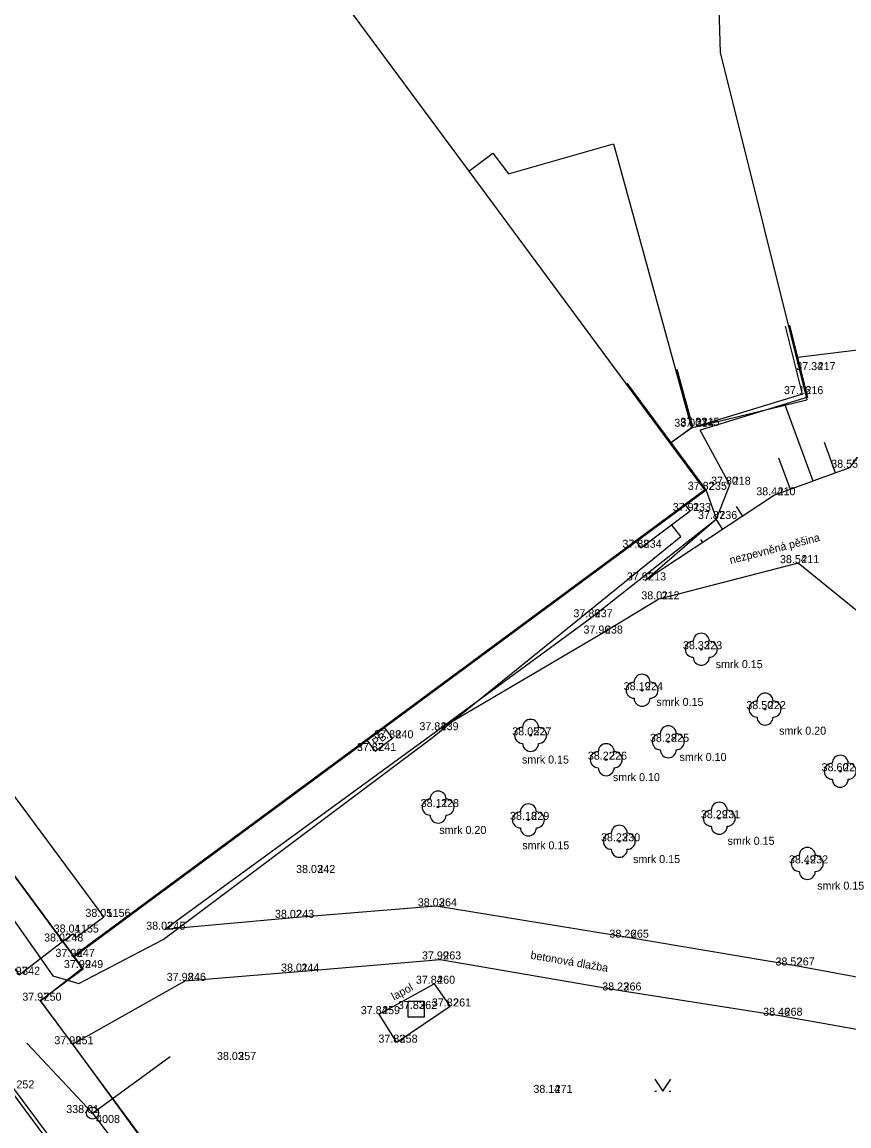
# Model space of a CAD drawing. Extents: x -609709 to -609357, y -1051535 to -1051131.
# Drawn here: x -609544.11 to -609518.29, y -1051297.25 to -1051262.77 of the extents above; entities that cross this region are included whole.
import ezdxf

# ---------------------------------------------------------------- set-up
doc = ezdxf.new("R2010")
doc.units = 0
for name, color, linetype in [('Vrstva 1', 7, 'Continuous'), ('Vrstva 10', 7, 'Continuous'), ('Vrstva 12', 7, 'Continuous'), ('Vrstva 18', 7, 'Continuous'), ('Vrstva 2', 7, 'Continuous'), ('Vrstva 3', 7, 'Continuous'), ('Vrstva 4', 7, 'Continuous'), ('Vrstva 5', 7, 'Continuous'), ('Vrstva 6', 7, 'Continuous'), ('Vrstva 7', 7, 'Continuous'), ('Vrstva 8', 7, 'Continuous'), ('Vrstva 9', 7, 'Continuous')]:
    doc.layers.add(name, color=color, linetype=linetype)

msp = doc.modelspace()

# ---------------------------------------------------------------- linework, layer by layer
at = {"layer": 'Vrstva 1'}
for p, q in [((-609519.36, -1051273.64), (-609519.36, -1051273.64)), ((-609519.74, -1051274.39), (-609519.74, -1051274.39)), ((-609523.16, -1051275.41), (-609523.16, -1051275.41)), ((-609522.98, -1051275.38), (-609522.98, -1051275.38)), ((-609522.01, -1051277.22), (-609522.01, -1051277.22)), ((-609522.75, -1051277.38), (-609522.75, -1051277.38)), ((-609520.61, -1051277.55), (-609520.61, -1051277.55)), ((-609523.25, -1051278.04), (-609523.25, -1051278.04)), ((-609522.43, -1051278.29), (-609522.43, -1051278.29)), ((-609524.79, -1051279.19), (-609524.79, -1051279.19)), ((-609519.87, -1051279.67), (-609519.87, -1051279.67)), ((-609524.65, -1051280.21), (-609524.65, -1051280.21)), ((-609524.23, -1051280.8), (-609524.23, -1051280.8)), ((-609526.32, -1051281.36), (-609526.32, -1051281.36)), ((-609526, -1051281.87), (-609526, -1051281.87)), ((-609522.9, -1051282.36), (-609522.9, -1051282.36)), ((-609524.75, -1051283.64), (-609524.75, -1051283.64)), ((-609520.91, -1051284.23), (-609520.91, -1051284.23)), ((-609532.54, -1051285.14), (-609532.54, -1051285.14)), ((-609531.13, -1051284.89), (-609531.13, -1051284.89)), ((-609528.23, -1051285.05), (-609528.23, -1051285.05)), ((-609533.08, -1051285.54), (-609533.08, -1051285.54)), ((-609523.93, -1051285.25), (-609523.93, -1051285.25)), ((-609525.87, -1051285.81), (-609525.87, -1051285.81)), ((-609518.56, -1051286.17), (-609518.56, -1051286.17)), ((-609531.12, -1051287.29), (-609531.12, -1051287.29)), ((-609528.3, -1051287.69), (-609528.3, -1051287.69)), ((-609522.34, -1051287.64), (-609522.34, -1051287.64)), ((-609525.46, -1051288.36), (-609525.46, -1051288.36)), ((-609534.98, -1051289.35), (-609534.98, -1051289.35)), ((-609519.59, -1051289.05), (-609519.59, -1051289.05)), ((-609531.18, -1051290.39), (-609531.18, -1051290.39)), ((-609541.56, -1051290.72), (-609541.56, -1051290.72)), ((-609535.64, -1051290.75), (-609535.64, -1051290.75)), ((-609542.55, -1051291.21), (-609542.55, -1051291.21)), ((-609539.66, -1051291.12), (-609539.66, -1051291.12)), ((-609525.19, -1051291.37), (-609525.19, -1051291.37)), ((-609542.85, -1051291.49), (-609542.85, -1051291.49)), ((-609542.49, -1051291.97), (-609542.49, -1051291.97)), ((-609531.05, -1051292.05), (-609531.05, -1051292.05)), ((-609542.23, -1051292.32), (-609542.23, -1051292.32)), ((-609535.48, -1051292.43), (-609535.48, -1051292.43)), ((-609520.01, -1051292.24), (-609520.01, -1051292.24)), ((-609539.02, -1051292.72), (-609539.02, -1051292.72)), ((-609531.24, -1051292.81), (-609531.24, -1051292.81)), ((-609525.42, -1051293.02), (-609525.42, -1051293.02)), ((-609543.53, -1051293.34), (-609543.53, -1051293.34)), ((-609532.96, -1051293.76), (-609532.96, -1051293.76)), ((-609531.8, -1051293.6), (-609531.8, -1051293.6)), ((-609530.74, -1051293.52), (-609530.74, -1051293.52)), ((-609520.39, -1051293.81), (-609520.39, -1051293.81)), ((-609542.53, -1051294.7), (-609542.53, -1051294.7)), ((-609532.41, -1051294.65), (-609532.41, -1051294.65)), ((-609537.45, -1051295.19), (-609537.45, -1051295.19)), ((-609527.57, -1051296.22), (-609527.57, -1051296.22)), ((-609541.91, -1051296.85), (-609541.91, -1051296.85))]:
    msp.add_line(p, q, dxfattribs=at)
at = {"layer": 'Vrstva 10'}
for p, q in [((-609573.93, -1051249.42), (-609542.5, -1051291.94)), ((-609522.44, -1051259.04), (-609522.31, -1051263.72)), ((-609535.71, -1051259.91), (-609530.16, -1051267.42)), ((-609522.31, -1051263.72), (-609519.6, -1051274.57)), ((-609528.92, -1051267.51), (-609525.64, -1051266.57)), ((-609525.64, -1051266.57), (-609523.21, -1051275.44)), ((-609530.16, -1051267.42), (-609529.41, -1051266.86)), ((-609529.41, -1051266.86), (-609528.92, -1051267.51)), ((-609530.16, -1051267.42), (-609523.88, -1051275.92)), ((-609523.21, -1051275.44), (-609519.6, -1051274.57)), ((-609523.88, -1051275.92), (-609523.21, -1051275.44)), ((-609523.88, -1051275.92), (-609522.8, -1051277.38)), ((-609542.5, -1051291.94), (-609522.8, -1051277.38)), ((-609550.03, -1051288.63), (-609523.24, -1051324.85)), ((-609542.5, -1051291.94), (-609542.2, -1051292.34)), ((-609543.54, -1051293.33), (-609542.2, -1051292.34)), ((-609543.54, -1051293.33), (-609521.35, -1051323.44)), ((-609524.35, -1051295.795), (-609524.1, -1051296.17)), ((-609524.1, -1051296.17), (-609523.85, -1051295.795)), ((-609524.35, -1051296.17), (-609524.3, -1051296.17)), ((-609523.9, -1051296.17), (-609523.85, -1051296.17))]:
    msp.add_line(p, q, dxfattribs=at)
at = {"layer": 'Vrstva 12'}
msp.add_lwpolyline([(-609555.76, -1051273.58), (-609551.67, -1051280.42), (-609543.15, -1051292.56), (-609542.34, -1051292.8), (-609539.7, -1051291.43), (-609531.29, -1051285.12), (-609523.54, -1051278.84), (-609523.841, -1051278.449)], dxfattribs=at)
at = {"layer": 'Vrstva 18'}
for points in [[(-609541.91, -1051296.85), (-609543.962, -1051294.662)], [(-609541.91, -1051296.85), (-609543.962, -1051294.662)], [(-609541.91, -1051296.85), (-609539.489, -1051295.078)], [(-609541.91, -1051296.85), (-609540.099, -1051299.242)]]:
    msp.add_lwpolyline(points, dxfattribs=at)
for radius in [0.188, 0.025]:
    msp.add_circle((-609541.91, -1051296.85), radius, dxfattribs=at)
at = {"layer": 'Vrstva 4'}
for q in [(-609520.135, -1051272.231), (-609522.939, -1051275.514)]:
    msp.add_line((-609519.572, -1051274.485), q, dxfattribs=at)
for points in [[(-609519.74, -1051274.39), (-609520.271, -1051272.265)], [(-609519.74, -1051274.39), (-609522.98, -1051275.38)], [(-609539.66, -1051291.12), (-609531.13, -1051284.89), (-609526.32, -1051281.36), (-609522.43, -1051278.29), (-609522.75, -1051277.38)], [(-609517.39, -1051281.69), (-609519.87, -1051279.67), (-609524.23, -1051280.8), (-609526, -1051281.87)], [(-609526, -1051281.87), (-609531.13, -1051284.89)], [(-609549.76, -1051288.75), (-609547.85, -1051291.29), (-609545.93, -1051293.92), (-609544.38, -1051296.08), (-609541.25, -1051300.29), (-609539.34, -1051302.91), (-609536.37, -1051306.73), (-609533.41, -1051311.01), (-609529.82, -1051315.81), (-609526.99, -1051319.64), (-609524.14, -1051323.52), (-609523.26, -1051324.77), (-609525.66, -1051326.48), (-609528.98, -1051328.94), (-609532.13, -1051331.13), (-609536.11, -1051333.93)], [(-609515.47, -1051294.69), (-609515.18, -1051293.14), (-609520.01, -1051292.24), (-609525.19, -1051291.37), (-609531.18, -1051290.39), (-609535.64, -1051290.75), (-609539.66, -1051291.12)], [(-609521.45, -1051323.51), (-609522.35, -1051322.21), (-609525.21, -1051318.31), (-609528.01, -1051314.48), (-609531.78, -1051309.4), (-609534.64, -1051305.47), (-609537.5, -1051301.63), (-609539.35, -1051299.05), (-609542.53, -1051294.7), (-609543.53, -1051293.34), (-609542.23, -1051292.32), (-609542.49, -1051291.97)], [(-609542.53, -1051294.7), (-609539.02, -1051292.72), (-609535.48, -1051292.43), (-609531.05, -1051292.05), (-609525.42, -1051293.02), (-609520.39, -1051293.81), (-609515.47, -1051294.69)]]:
    msp.add_lwpolyline(points, dxfattribs=at)
at = {"layer": 'Vrstva 5'}
for points in [[(-609533.08, -1051285.54), (-609532.54, -1051285.14), (-609532.791, -1051284.801)], [(-609533.08, -1051285.54), (-609533.331, -1051285.2)], [(-609548.68, -1051286.55), (-609546.5, -1051289.51), (-609544.2, -1051292.53), (-609542.85, -1051291.49)], [(-609532.41, -1051294.65), (-609532.96, -1051293.76), (-609531.24, -1051292.81), (-609530.74, -1051293.52), (-609532.41, -1051294.65)]]:
    msp.add_lwpolyline(points, dxfattribs=at)
msp.add_lwpolyline([(-609532.05, -1051293.35), (-609531.55, -1051293.35), (-609531.55, -1051293.85), (-609532.05, -1051293.85)], close=True, dxfattribs=at)
at = {"layer": 'Vrstva 6'}
for points in [[(-609517.14, -1051271.58), (-609516.77, -1051274.6), (-609518.27, -1051276.69), (-609520.61, -1051277.55), (-609524.65, -1051280.21)], [(-609524.65, -1051280.21), (-609522.43, -1051278.29), (-609522.01, -1051277.22), (-609522.939, -1051275.514)]]:
    msp.add_lwpolyline(points, dxfattribs=at)
at = {"layer": 'Vrstva 7'}
for centre in [(-609522.9, -1051282.36), (-609524.75, -1051283.64), (-609520.91, -1051284.23), (-609528.23, -1051285.05), (-609523.93, -1051285.25), (-609525.87, -1051285.81), (-609518.56, -1051286.17), (-609531.12, -1051287.29), (-609522.34, -1051287.64), (-609528.3, -1051287.69), (-609525.46, -1051288.36), (-609519.59, -1051289.05)]:
    msp.add_circle(centre, 0.025, dxfattribs=at)
for centre, start, end in [((-609523.15, -1051282.36), 90, 270), ((-609522.9, -1051282.11), 0, 180), ((-609522.65, -1051282.36), 270, 90), ((-609522.9, -1051282.61), 180, 0), ((-609524.75, -1051283.39), 0, 180), ((-609525, -1051283.64), 90, 270), ((-609524.5, -1051283.64), 270, 90), ((-609520.91, -1051283.98), 0, 180), ((-609524.75, -1051283.89), 180, 0), ((-609521.16, -1051284.23), 90, 270), ((-609520.66, -1051284.23), 270, 90), ((-609520.91, -1051284.48), 180, 0), ((-609528.48, -1051285.05), 90, 270), ((-609528.23, -1051284.8), 0, 180), ((-609527.98, -1051285.05), 270, 90), ((-609523.93, -1051285), 0, 180), ((-609524.18, -1051285.25), 90, 270), ((-609523.68, -1051285.25), 270, 90), ((-609528.23, -1051285.3), 180, 0), ((-609526.12, -1051285.81), 90, 270), ((-609525.87, -1051285.56), 0, 180), ((-609525.62, -1051285.81), 270, 90), ((-609523.93, -1051285.5), 180, 0), ((-609518.56, -1051285.92), 0, 180), ((-609525.87, -1051286.06), 180, 0), ((-609518.81, -1051286.17), 90, 270), ((-609518.31, -1051286.17), 270, 90), ((-609518.56, -1051286.42), 180, 0), ((-609531.12, -1051287.04), 0, 180), ((-609531.37, -1051287.29), 90, 270), ((-609530.87, -1051287.29), 270, 90), ((-609528.3, -1051287.44), 0, 180), ((-609522.34, -1051287.39), 0, 180), ((-609531.12, -1051287.54), 180, 0), ((-609528.55, -1051287.69), 90, 270), ((-609528.05, -1051287.69), 270, 90), ((-609522.59, -1051287.64), 90, 270), ((-609522.09, -1051287.64), 270, 90), ((-609528.3, -1051287.94), 180, 0), ((-609525.46, -1051288.11), 0, 180), ((-609522.34, -1051287.89), 180, 0), ((-609525.71, -1051288.36), 90, 270), ((-609525.21, -1051288.36), 270, 90), ((-609525.46, -1051288.61), 180, 0), ((-609519.59, -1051288.8), 0, 180), ((-609519.84, -1051289.05), 90, 270), ((-609519.34, -1051289.05), 270, 90), ((-609519.59, -1051289.3), 180, 0)]:
    msp.add_arc(centre, 0.25, start, end, dxfattribs=at)
at = {"layer": 'Vrstva 8'}
for p, q in [((-609516.979, -1051272.89), (-609519.881, -1051273.246)), ((-609519.411, -1051277.109), (-609520.295, -1051274.706)), ((-609518.707, -1051276.851), (-609519.055, -1051275.905)), ((-609520.115, -1051277.368), (-609520.474, -1051276.391)), ((-609521.602, -1051278.203), (-609521.801, -1051277.901)), ((-609522.229, -1051278.616), (-609522.438, -1051278.297)), ((-609522.855, -1051279.028), (-609522.917, -1051278.934))]:
    msp.add_line(p, q, dxfattribs=at)
at = {"layer": 'Vrstva 9'}
for points in [[(-609564.23, -1051262.48), (-609542.85, -1051291.49)], [(-609523.16, -1051275.41), (-609523.65, -1051273.62)], [(-609522.75, -1051277.38), (-609525.212, -1051274.048)], [(-609523.16, -1051275.41), (-609523.836, -1051275.91)], [(-609542.85, -1051291.49), (-609542.49, -1051291.97), (-609522.75, -1051277.38)], [(-609524.934, -1051278.995), (-609524.79, -1051279.19), (-609523.25, -1051278.04), (-609523.389, -1051277.852)], [(-609542.522, -1051291.248), (-609542.434, -1051291.366), (-609541.56, -1051290.72), (-609546.074, -1051284.624)], [(-609542.85, -1051291.49), (-609542.522, -1051291.248)]]:
    msp.add_lwpolyline(points, dxfattribs=at)

# ---------------------------------------------------------------- texts
at = {"layer": 'Vrstva 18'}
msp.add_text(' 4008', height=0.25, dxfattribs=at).set_placement((-609541.89, -1051297.16))
at = {"layer": 'Vrstva 2'}
for s, p in [(' 217', (-609519.36, -1051273.64)), (' 216', (-609519.74, -1051274.39)), (' 214', (-609523.16, -1051275.41)), (' 215', (-609522.98, -1051275.38)), (' 235', (-609522.75, -1051277.38)), (' 218', (-609522.01, -1051277.22)), (' 210', (-609520.61, -1051277.55)), (' 233', (-609523.25, -1051278.04)), (' 236', (-609522.43, -1051278.29)), (' 234', (-609524.79, -1051279.19)), (' 211', (-609519.87, -1051279.67)), (' 213', (-609524.65, -1051280.21)), (' 212', (-609524.23, -1051280.8)), (' 237', (-609526.32, -1051281.36)), (' 238', (-609526, -1051281.87)), (' 223', (-609522.9, -1051282.36)), (' 224', (-609524.75, -1051283.64)), (' 222', (-609520.91, -1051284.23)), (' 239', (-609531.13, -1051284.89)), (' 227', (-609528.23, -1051285.05)), (' 240', (-609532.54, -1051285.14)), (' 225', (-609523.93, -1051285.25)), (' 241', (-609533.08, -1051285.54)), (' 226', (-609525.87, -1051285.81)), (' 221', (-609518.56, -1051286.17)), (' 228', (-609531.12, -1051287.29)), (' 229', (-609528.3, -1051287.69)), (' 231', (-609522.34, -1051287.64)), (' 230', (-609525.46, -1051288.36)), (' 232', (-609519.59, -1051289.05)), (' 242', (-609534.98, -1051289.35)), (' 264', (-609531.18, -1051290.39)), (' 1156', (-609541.56, -1051290.72)), (' 243', (-609535.64, -1051290.75)), (' 1155', (-609542.55, -1051291.21)), (' 245', (-609539.66, -1051291.12)), (' 248', (-609542.85, -1051291.49)), (' 265', (-609525.19, -1051291.37)), (' 247', (-609542.49, -1051291.97)), (' 249', (-609542.23, -1051292.32)), (' 263', (-609531.05, -1051292.05)), (' 267', (-609520.01, -1051292.24)), (' 342', (-609544.2, -1051292.53)), (' 246', (-609539.02, -1051292.72)), (' 244', (-609535.48, -1051292.43)), (' 260', (-609531.24, -1051292.81)), (' 266', (-609525.42, -1051293.02)), (' 250', (-609543.53, -1051293.34)), (' 262', (-609531.8, -1051293.6)), (' 261', (-609530.74, -1051293.52)), (' 259', (-609532.96, -1051293.76)), (' 268', (-609520.39, -1051293.81)), (' 251', (-609542.53, -1051294.7)), (' 258', (-609532.41, -1051294.65)), (' 257', (-609537.45, -1051295.19)), (' 252', (-609544.38, -1051296.08)), (' 271', (-609527.57, -1051296.22))]:
    msp.add_text(s, height=0.25, dxfattribs=at).set_placement(p)
at = {"layer": 'Vrstva 3'}
for s, p in [('37.34', (-609519.933, -1051273.64)), ('37.16', (-609520.319, -1051274.39)), ('38.00', (-609523.743, -1051275.41)), ('37.33', (-609523.553, -1051275.38)), ('38.55', (-609518.843, -1051276.69)), ('37.82', (-609523.323, -1051277.38)), ('37.80', (-609522.593, -1051277.22)), ('38.44', (-609521.183, -1051277.55)), ('37.91', (-609523.792, -1051278.04)), ('37.87', (-609523.003, -1051278.29)), ('37.88', (-609525.363, -1051279.19)), ('38.54', (-609520.443, -1051279.67)), ('37.92', (-609525.223, -1051280.21)), ('38.01', (-609524.772, -1051280.8)), ('37.89', (-609526.893, -1051281.36)), ('37.96', (-609526.579, -1051281.87)), ('38.33', (-609523.473, -1051282.36)), ('38.19', (-609525.323, -1051283.64)), ('38.50', (-609521.493, -1051284.23)), ('37.84', (-609531.703, -1051284.89)), ('38.05', (-609528.803, -1051285.05)), ('37.88', (-609533.113, -1051285.14)), ('38.28', (-609524.503, -1051285.25)), ('37.87', (-609533.653, -1051285.54)), ('38.22', (-609526.443, -1051285.81)), ('38.60', (-609519.143, -1051286.17)), ('38.11', (-609531.662, -1051287.29)), ('38.18', (-609528.873, -1051287.69)), ('38.29', (-609522.913, -1051287.64)), ('38.23', (-609526.033, -1051288.36)), ('38.49', (-609520.163, -1051289.05)), ('38.03', (-609535.553, -1051289.35)), ('38.03', (-609531.753, -1051290.39)), ('38.05', (-609542.133, -1051290.72)), ('38.02', (-609536.213, -1051290.75)), ('38.04', (-609543.123, -1051291.21)), ('38.02', (-609540.233, -1051291.12)), ('38.02', (-609543.423, -1051291.49)), ('38.26', (-609525.769, -1051291.37)), ('37.96', (-609543.069, -1051291.97)), ('37.99', (-609542.803, -1051292.32)), ('37.99', (-609531.623, -1051292.05)), ('38.52', (-609520.583, -1051292.24)), ('37.97', (-609544.773, -1051292.53)), ('37.98', (-609539.593, -1051292.72)), ('38.01', (-609536.022, -1051292.43)), ('37.84', (-609531.813, -1051292.81)), ('38.23', (-609525.993, -1051293.02)), ('37.97', (-609544.103, -1051293.34)), ('37.83', (-609532.373, -1051293.6)), ('37.82', (-609531.313, -1051293.52)), ('37.84', (-609533.533, -1051293.76)), ('38.46', (-609520.969, -1051293.81)), ('37.98', (-609543.103, -1051294.7)), ('37.83', (-609532.983, -1051294.65)), ('38.03', (-609538.023, -1051295.19)), ('38.14', (-609528.143, -1051296.22)), ('338.01', (-609542.73, -1051296.85))]:
    msp.add_text(s, height=0.25, dxfattribs=at).set_placement(p)
at = {"layer": 'Vrstva 4'}
for s, rotation, p in [('nezpevněná pěšina', 14.5299, (-609521.984, -1051279.701)), ('betonová dlažba', 350.2244, (-609528.247, -1051292.026))]:
    msp.add_text(s, height=0.25, rotation=rotation, dxfattribs=at).set_placement(p)
at = {"layer": 'Vrstva 5'}
for s, rotation, p in [('PB', 36.5289, (-609533.064, -1051285.403)), ('lapol', 28.913, (-609532.492, -1051293.34))]:
    msp.add_text(s, height=0.25, rotation=rotation, dxfattribs=at).set_placement(p)
at = {"layer": 'Vrstva 7'}
for s, p in [('smrk 0.15', (-609522.45, -1051282.95)), ('smrk 0.15', (-609524.3, -1051284.13)), ('smrk 0.20', (-609520.47, -1051285.03)), ('smrk 0.15', (-609528.5, -1051285.93)), ('smrk 0.10', (-609523.58, -1051285.85)), ('smrk 0.10', (-609525.66, -1051286.48)), ('smrk 0.20', (-609531.08, -1051288.13)), ('smrk 0.15', (-609522.08, -1051288.47)), ('smrk 0.15', (-609528.49, -1051288.61)), ('smrk 0.15', (-609525.03, -1051289.04)), ('smrk 0.15', (-609519.28, -1051289.87))]:
    msp.add_text(s, height=0.25, dxfattribs=at).set_placement(p)

doc.saveas('drawing.dxf')
